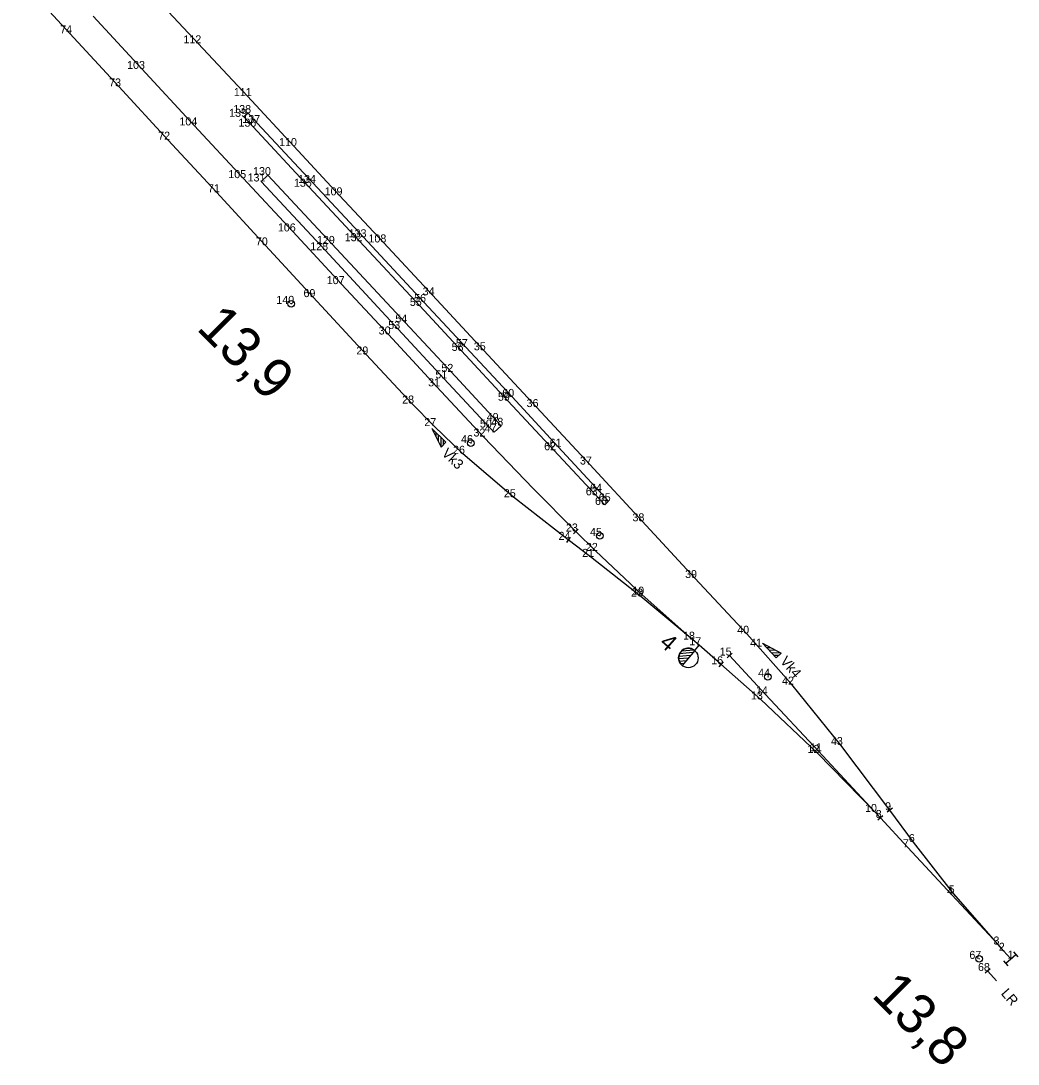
# Model space of a CAD drawing. Extents: x -554814 to -554052, y -1115925 to -1115523.
# Drawn here: x -554387.5 to -554238, y -1115862.7 to -1115706.4 of the extents above; entities that cross this region are included whole.
import ezdxf

# ---------------------------------------------------------------- set-up
doc = ezdxf.new("R2010")
doc.units = 0
for name, color, linetype in [('Vrstva 1', 7, 'Continuous'), ('Vrstva 14', 7, 'Continuous'), ('Vrstva 2', 7, 'Continuous'), ('Vrstva 3', 7, 'Continuous'), ('Vrstva 50', 7, 'Continuous'), ('Vrstva 6', 7, 'Continuous'), ('Vrstva 60', 7, 'Continuous'), ('Vrstva 7', 7, 'Continuous')]:
    doc.layers.add(name, color=color, linetype=linetype)

msp = doc.modelspace()

# ---------------------------------------------------------------- linework, layer by layer
at = {"layer": 'Vrstva 1'}
msp.add_line((-554239.09, -1115846.92), (-554240.2, -1115845.72), dxfattribs=at)
for points in [[(-554285.83, -1115799.93), (-554286.77, -1115799.1), (-554294.58, -1115792.63), (-554302.09, -1115786.69), (-554305.44, -1115784.14), (-554313.63, -1115777.75), (-554321.25, -1115771.24), (-554325.56, -1115767.1), (-554328.88, -1115763.71), (-554335.73, -1115756.36), (-554343.66, -1115747.76), (-554350.81, -1115740.01), (-554358.18, -1115732.04), (-554365.45, -1115724.17), (-554372.81, -1115716.19), (-554380.14, -1115708.23), (-554387.49, -1115700.26)], [(-554240.2, -1115845.72), (-554241.01, -1115844.79), (-554247.71, -1115837.12), (-554253.7, -1115829.42), (-554257.24, -1115824.66), (-554264.6, -1115814.89), (-554271.95, -1115805.84), (-554278.66, -1115798.21), (-554286.46, -1115789.86), (-554294.36, -1115781.36), (-554302.23, -1115772.85), (-554310.22, -1115764.24), (-554318.13, -1115755.73), (-554325.8, -1115747.48), (-554333.16, -1115739.57), (-554339.73, -1115732.51), (-554346.57, -1115725.12), (-554353.53, -1115717.63), (-554360.91, -1115709.73), (-554367.59, -1115702.57)], [(-554285.83, -1115799.93), (-554286.77, -1115799.1), (-554294.37, -1115792.36), (-554301.34, -1115785.8), (-554304.33, -1115782.89), (-554310.66, -1115776.49), (-554318.19, -1115768.65), (-554325.17, -1115761.14), (-554332.4, -1115753.36), (-554339.41, -1115745.81), (-554346.74, -1115737.92), (-554354.16, -1115729.93), (-554361.5, -1115722.03), (-554369.34, -1115713.57), (-554376.66, -1115705.67)], [(-554258.66, -1115825.82), (-554259.49, -1115824.92), (-554268.14, -1115816.07), (-554276.6, -1115808.06), (-554282.56, -1115802.79), (-554285.83, -1115799.93)], [(-554258.66, -1115825.82), (-554259.49, -1115824.92), (-554267.94, -1115815.83), (-554275.86, -1115807.31), (-554281.27, -1115801.48)], [(-554240.2, -1115845.72), (-554241.01, -1115844.79), (-554247.96, -1115837.35), (-554254.6, -1115830.2), (-554258.66, -1115825.82)]]:
    msp.add_lwpolyline(points, dxfattribs=at)
at = {"layer": 'Vrstva 14'}
msp.add_lwpolyline([(-554299.98, -1115778.91), (-554299.4, -1115778.36), (-554300.71, -1115776.92), (-554306.96, -1115770.18), (-554313.87, -1115762.72), (-554320.82, -1115755.24), (-554327.09, -1115748.51), (-554336.13, -1115738.79), (-554343.72, -1115730.65), (-554352.07, -1115721.67), (-554353.43, -1115720.18), (-554354.05, -1115720.74), (-554352.65, -1115722.22), (-554344.33, -1115731.22), (-554336.73, -1115739.38), (-554327.71, -1115749.08), (-554321.45, -1115755.82), (-554314.52, -1115763.29), (-554307.6, -1115770.71), (-554299.98, -1115778.91)], dxfattribs=at)
msp.add_lwpolyline([(-554315.5, -1115767.05), (-554316.2, -1115766.32), (-554323, -1115758.97), (-554329.9, -1115751.57), (-554340.88, -1115739.79), (-554350.46, -1115729.48), (-554351.47, -1115730.43), (-554341.89, -1115740.74), (-554330.95, -1115752.54), (-554324.09, -1115759.94), (-554317.23, -1115767.31), (-554316.53, -1115768.02)], close=True, dxfattribs=at)
at = {"layer": 'Vrstva 2'}
for p, q in [((-554305.14, -1115783.73), (-554305.73, -1115784.54)), ((-554303.98, -1115782.53), (-554304.68, -1115783.25)), ((-554286.59, -1115800.65), (-554288.48, -1115800.81)), ((-554286.49, -1115800.72), (-554288.38, -1115802.96)), ((-554286.49, -1115800.71), (-554285.83, -1115799.93)), ((-554286.49, -1115800.71), (-554286.49, -1115800.72)), ((-554287.45, -1115801.85), (-554288.89, -1115801.98)), ((-554287.11, -1115801.45), (-554288.88, -1115801.6)), ((-554287.79, -1115802.26), (-554288.8, -1115802.35)), ((-554286.77, -1115801.04), (-554288.76, -1115801.21)), ((-554282.24, -1115802.41), (-554282.88, -1115803.17)), ((-554280.9, -1115801.14), (-554281.64, -1115801.81)), ((-554288.13, -1115802.67), (-554288.61, -1115802.71)), ((-554256.85, -1115824.35), (-554257.64, -1115824.97)), ((-554258.29, -1115825.48), (-554259.02, -1115826.16))]:
    msp.add_line(p, q, dxfattribs=at)
msp.add_circle((-554287.44, -1115801.84), 1.46, dxfattribs=at)
msp.add_arc((-554287.44, -1115801.84), 1.46, 50.0196, 229.9804, dxfattribs=at)
at = {"layer": 'Vrstva 3'}
for p, q in [((-554325.68, -1115767.68), (-554325.67, -1115767.93)), ((-554325.3, -1115768.05), (-554325.3, -1115768.67)), ((-554324.93, -1115768.42), (-554324.93, -1115769.39)), ((-554324.55, -1115768.79), (-554324.55, -1115770.13)), ((-554324.18, -1115769.15), (-554324.18, -1115769.91)), ((-554323.81, -1115769.52), (-554323.82, -1115769.53)), ((-554276.09, -1115799.86), (-554275.85, -1115799.87)), ((-554275.73, -1115800.25), (-554275.12, -1115800.27)), ((-554275.37, -1115800.63), (-554274.38, -1115800.67)), ((-554275.01, -1115801.02), (-554273.65, -1115801.08)), ((-554274.65, -1115801.41), (-554273.88, -1115801.44)), ((-554274.29, -1115801.8), (-554274.27, -1115801.8)), ((-554239.84, -1115847.58), (-554238.34, -1115846.26)), ((-554238.01, -1115846.63), (-554238.67, -1115845.88)), ((-554239.51, -1115847.96), (-554240.17, -1115847.21))]:
    msp.add_line(p, q, dxfattribs=at)
for points in [[(-554325.91, -1115767.46), (-554324.5, -1115770.23), (-554323.8, -1115769.52), (-554325.91, -1115767.46)], [(-554276.32, -1115799.61), (-554273.55, -1115801.13), (-554274.28, -1115801.81), (-554276.32, -1115799.61)]]:
    msp.add_lwpolyline(points, dxfattribs=at)
at = {"layer": 'Vrstva 50'}
for p, q in [((-554320.08, -1115769.59), (-554320.01, -1115769.66)), ((-554300.75, -1115783.51), (-554300.67, -1115783.58)), ((-554275.55, -1115804.62), (-554275.49, -1115804.7))]:
    msp.add_line(p, q, dxfattribs=at)
for centre in [(-554320.04, -1115769.63), (-554300.71, -1115783.54), (-554275.52, -1115804.66)]:
    msp.add_circle(centre, 0.5, dxfattribs=at)
at = {"layer": 'Vrstva 6'}
for p, q in [((-554242.19, -1115848.42), (-554242.93, -1115849.1)), ((-554241.23, -1115850.22), (-554242.56, -1115848.76))]:
    msp.add_line(p, q, dxfattribs=at)
at = {"layer": 'Vrstva 60'}
for p, q in [((-554380.14, -1115708.23), (-554380.14, -1115708.23)), ((-554360.91, -1115709.73), (-554360.91, -1115709.73)), ((-554369.34, -1115713.57), (-554369.34, -1115713.57)), ((-554372.81, -1115716.19), (-554372.81, -1115716.19)), ((-554353.53, -1115717.63), (-554353.53, -1115717.63)), ((-554354.05, -1115720.74), (-554354.05, -1115720.74)), ((-554353.43, -1115720.18), (-554353.43, -1115720.18)), ((-554361.5, -1115722.03), (-554361.5, -1115722.03)), ((-554352.65, -1115722.22), (-554352.65, -1115722.22)), ((-554352.07, -1115721.67), (-554352.07, -1115721.67)), ((-554365.45, -1115724.17), (-554365.45, -1115724.17)), ((-554346.57, -1115725.12), (-554346.57, -1115725.12)), ((-554354.16, -1115729.93), (-554354.16, -1115729.93)), ((-554351.47, -1115730.43), (-554351.47, -1115730.43)), ((-554350.46, -1115729.48), (-554350.46, -1115729.48)), ((-554358.18, -1115732.04), (-554358.18, -1115732.04)), ((-554344.33, -1115731.22), (-554344.33, -1115731.22)), ((-554343.72, -1115730.65), (-554343.72, -1115730.65)), ((-554339.73, -1115732.51), (-554339.73, -1115732.51)), ((-554346.74, -1115737.92), (-554346.74, -1115737.92)), ((-554340.88, -1115739.79), (-554340.88, -1115739.79)), ((-554336.73, -1115739.38), (-554336.73, -1115739.38)), ((-554336.13, -1115738.79), (-554336.13, -1115738.79)), ((-554333.16, -1115739.57), (-554333.16, -1115739.57)), ((-554350.81, -1115740.01), (-554350.81, -1115740.01)), ((-554341.89, -1115740.74), (-554341.89, -1115740.74)), ((-554339.41, -1115745.81), (-554339.41, -1115745.81)), ((-554343.66, -1115747.76), (-554343.66, -1115747.76)), ((-554325.8, -1115747.48), (-554325.8, -1115747.48)), ((-554346.98, -1115748.77), (-554346.98, -1115748.77)), ((-554327.71, -1115749.08), (-554327.71, -1115749.08)), ((-554327.09, -1115748.51), (-554327.09, -1115748.51)), ((-554329.9, -1115751.57), (-554329.9, -1115751.57)), ((-554332.4, -1115753.36), (-554332.4, -1115753.36)), ((-554330.95, -1115752.54), (-554330.95, -1115752.54)), ((-554320.82, -1115755.24), (-554320.82, -1115755.24)), ((-554335.73, -1115756.36), (-554335.73, -1115756.36)), ((-554321.45, -1115755.82), (-554321.45, -1115755.82)), ((-554318.13, -1115755.73), (-554318.13, -1115755.73)), ((-554324.09, -1115759.94), (-554324.09, -1115759.94)), ((-554323, -1115758.97), (-554323, -1115758.97)), ((-554325.17, -1115761.14), (-554325.17, -1115761.14)), ((-554314.52, -1115763.29), (-554314.52, -1115763.29)), ((-554313.87, -1115762.72), (-554313.87, -1115762.72)), ((-554328.88, -1115763.71), (-554328.88, -1115763.71)), ((-554310.22, -1115764.24), (-554310.22, -1115764.24)), ((-554316.2, -1115766.32), (-554316.2, -1115766.32)), ((-554325.56, -1115767.1), (-554325.56, -1115767.1)), ((-554317.23, -1115767.31), (-554317.23, -1115767.31)), ((-554316.53, -1115768.02), (-554316.53, -1115768.02)), ((-554315.5, -1115767.05), (-554315.5, -1115767.05)), ((-554320.04, -1115769.63), (-554320.04, -1115769.63)), ((-554318.19, -1115768.65), (-554318.19, -1115768.65)), ((-554321.25, -1115771.24), (-554321.25, -1115771.24)), ((-554307.6, -1115770.71), (-554307.6, -1115770.71)), ((-554306.96, -1115770.18), (-554306.96, -1115770.18)), ((-554302.23, -1115772.85), (-554302.23, -1115772.85)), ((-554310.66, -1115776.49), (-554310.66, -1115776.49)), ((-554301.35, -1115777.46), (-554301.35, -1115777.46)), ((-554300.71, -1115776.92), (-554300.71, -1115776.92)), ((-554313.63, -1115777.75), (-554313.63, -1115777.75)), ((-554299.98, -1115778.91), (-554299.98, -1115778.91)), ((-554299.4, -1115778.36), (-554299.4, -1115778.36)), ((-554294.36, -1115781.36), (-554294.36, -1115781.36)), ((-554304.33, -1115782.89), (-554304.33, -1115782.89)), ((-554300.71, -1115783.54), (-554300.71, -1115783.54)), ((-554305.44, -1115784.14), (-554305.44, -1115784.14)), ((-554302.09, -1115786.69), (-554302.09, -1115786.69)), ((-554301.34, -1115785.8), (-554301.34, -1115785.8)), ((-554286.46, -1115789.86), (-554286.46, -1115789.86)), ((-554294.58, -1115792.63), (-554294.58, -1115792.63)), ((-554294.37, -1115792.36), (-554294.37, -1115792.36)), ((-554286.77, -1115799.1), (-554286.77, -1115799.1)), ((-554278.66, -1115798.21), (-554278.66, -1115798.21)), ((-554285.83, -1115799.93), (-554285.83, -1115799.93)), ((-554276.91, -1115800.15), (-554276.91, -1115800.15)), ((-554281.27, -1115801.48), (-554281.27, -1115801.48)), ((-554282.56, -1115802.79), (-554282.56, -1115802.79)), ((-554275.52, -1115804.66), (-554275.52, -1115804.66)), ((-554271.95, -1115805.84), (-554271.95, -1115805.84)), ((-554276.6, -1115808.06), (-554276.6, -1115808.06)), ((-554275.86, -1115807.31), (-554275.86, -1115807.31)), ((-554264.6, -1115814.89), (-554264.6, -1115814.89)), ((-554268.14, -1115816.07), (-554268.14, -1115816.07)), ((-554267.94, -1115815.83), (-554267.94, -1115815.83)), ((-554259.49, -1115824.92), (-554259.49, -1115824.92)), ((-554258.66, -1115825.82), (-554258.66, -1115825.82)), ((-554257.24, -1115824.66), (-554257.24, -1115824.66)), ((-554254.6, -1115830.2), (-554254.6, -1115830.2)), ((-554253.7, -1115829.42), (-554253.7, -1115829.42)), ((-554247.96, -1115837.35), (-554247.96, -1115837.35)), ((-554247.71, -1115837.12), (-554247.71, -1115837.12)), ((-554241.01, -1115844.79), (-554241.01, -1115844.79)), ((-554240.2, -1115845.72), (-554240.2, -1115845.72)), ((-554243.86, -1115846.94), (-554243.86, -1115846.94)), ((-554239.09, -1115846.92), (-554239.09, -1115846.92)), ((-554242.56, -1115848.76), (-554242.56, -1115848.76))]:
    msp.add_line(p, q, dxfattribs=at)
at = {"layer": 'Vrstva 7'}
for p, q in [((-554346.94, -1115748.81), (-554347.01, -1115748.73)), ((-554243.82, -1115846.98), (-554243.89, -1115846.9))]:
    msp.add_line(p, q, dxfattribs=at)
for centre in [(-554346.98, -1115748.77), (-554243.86, -1115846.94)]:
    msp.add_circle(centre, 0.5, dxfattribs=at)

# ---------------------------------------------------------------- texts
at = {"layer": 'Vrstva 2'}
msp.add_text('4', height=2.5, rotation=318.4553, dxfattribs=at).set_placement((-554291.92, -1115799.8))
at = {"layer": 'Vrstva 3'}
for s, rotation, p in [('Vk3', 316.1794, (-554324.51, -1115771.31)), ('Vk4', 311.3292, (-554273.78, -1115802.39))]:
    msp.add_text(s, height=1.5, rotation=rotation, dxfattribs=at).set_placement(p)
at = {"layer": 'Vrstva 6'}
msp.add_text('LR', height=1.5, rotation=311.1212, dxfattribs=at).set_placement((-554240.67, -1115852.17))
at = {"layer": 'Vrstva 60'}
for s, p in [('74', (-554381.6, -1115708.23)), ('112', (-554363.13, -1115709.73)), ('103', (-554371.57, -1115713.57)), ('73', (-554374.27, -1115716.19)), ('111', (-554355.57, -1115717.63)), ('139', (-554356.28, -1115720.74)), ('138', (-554355.66, -1115720.18)), ('104', (-554363.73, -1115722.03)), ('136', (-554354.88, -1115722.22)), ('137', (-554354.3, -1115721.67)), ('72', (-554366.91, -1115724.17)), ('110', (-554348.79, -1115725.12)), ('105', (-554356.4, -1115729.93)), ('130', (-554352.69, -1115729.48)), ('131', (-554353.51, -1115730.43)), ('135', (-554346.57, -1115731.22)), ('134', (-554345.94, -1115730.65)), ('71', (-554359.45, -1115732.04)), ('109', (-554341.96, -1115732.51)), ('106', (-554348.97, -1115737.92)), ('132', (-554338.95, -1115739.38)), ('133', (-554338.36, -1115738.79)), ('108', (-554335.39, -1115739.57)), ('70', (-554352.27, -1115740.01)), ('128', (-554344.12, -1115740.74)), ('129', (-554343.11, -1115739.79)), ('107', (-554341.64, -1115745.81)), ('34', (-554327.26, -1115747.48)), ('140', (-554349.2, -1115748.77)), ('69', (-554345.13, -1115747.76)), ('56', (-554328.55, -1115748.51)), ('55', (-554329.19, -1115749.08)), ('54', (-554331.36, -1115751.57)), ('30', (-554333.86, -1115753.36)), ('53', (-554332.42, -1115752.54)), ('57', (-554322.29, -1115755.24)), ('29', (-554337.2, -1115756.36)), ('58', (-554322.92, -1115755.82)), ('35', (-554319.6, -1115755.73)), ('51', (-554325.36, -1115759.94)), ('52', (-554324.46, -1115758.97)), ('31', (-554326.45, -1115761.14)), ('60', (-554315.33, -1115762.72)), ('28', (-554330.34, -1115763.71)), ('59', (-554315.99, -1115763.29)), ('36', (-554311.69, -1115764.24)), ('27', (-554327.02, -1115767.1)), ('50', (-554318.69, -1115767.31)), ('49', (-554317.67, -1115766.32)), ('48', (-554316.97, -1115767.05)), ('32', (-554319.65, -1115768.65)), ('47', (-554318, -1115768.02)), ('46', (-554321.51, -1115769.63)), ('62', (-554309.06, -1115770.71)), ('61', (-554308.23, -1115770.18)), ('26', (-554322.71, -1115771.24)), ('37', (-554303.69, -1115772.85)), ('64', (-554302.17, -1115776.92)), ('25', (-554315.1, -1115777.75)), ('63', (-554302.82, -1115777.46)), ('65', (-554300.87, -1115778.36)), ('66', (-554301.44, -1115778.91)), ('38', (-554295.82, -1115781.36)), ('23', (-554305.79, -1115782.89)), ('24', (-554306.9, -1115784.14)), ('45', (-554302.18, -1115783.54)), ('22', (-554302.8, -1115785.8)), ('21', (-554303.36, -1115786.69)), ('39', (-554287.93, -1115789.86)), ('20', (-554296.04, -1115792.63)), ('19', (-554295.84, -1115792.36)), ('40', (-554280.12, -1115798.21)), ('18', (-554288.24, -1115799.1)), ('17', (-554287.3, -1115799.93)), ('41', (-554278.18, -1115800.15)), ('15', (-554282.74, -1115801.48)), ('16', (-554284.02, -1115802.79)), ('44', (-554276.98, -1115804.66)), ('42', (-554273.4, -1115805.84)), ('13', (-554278.06, -1115808.06)), ('14', (-554277.32, -1115807.31)), ('12', (-554269.59, -1115816.07)), ('11', (-554269.21, -1115815.83)), ('43', (-554266.07, -1115814.89)), ('10', (-554260.96, -1115824.92)), ('9', (-554257.95, -1115824.66)), ('8', (-554259.36, -1115825.82)), ('7', (-554255.29, -1115830.2)), ('6', (-554254.4, -1115829.42)), ('4', (-554248.66, -1115837.35)), ('5', (-554248.42, -1115837.12)), ('3', (-554241.71, -1115844.79)), ('2', (-554240.9, -1115845.72)), ('67', (-554245.32, -1115846.94)), ('1', (-554239.6, -1115846.92)), ('68', (-554244.03, -1115848.76))]:
    msp.add_text(s, height=1.2, dxfattribs=at).set_placement(p)
at = {"layer": 'Vrstva 7'}
for s, p in [('13,9', (-554361.32, -1115752.55)), ('13,8', (-554260.15, -1115852.51))]:
    msp.add_text(s, height=6, rotation=315, dxfattribs=at).set_placement(p)

doc.saveas('drawing.dxf')
